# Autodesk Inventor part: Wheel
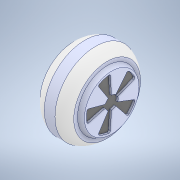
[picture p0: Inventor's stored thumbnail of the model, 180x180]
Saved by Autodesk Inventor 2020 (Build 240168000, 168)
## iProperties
Created: 2020-04
Part Number: Wheel
Material: Générique
Document SubType Name: Modeling
Designer: bruno
Density: 1 g/cm^3
Appearance: Par défaut
Sending System: SolidWorks 2017
Last Author: hpras
Last Saved: 2020-04-23
Author: bruno
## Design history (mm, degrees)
feature "CirPattern2"
sketch "Esquisse1"
  geometry: C1 r 12.7 at (0, 0); A1 r 12.7 centre (0, 0) between (6.917, -10.651) and (11.413, -5.57) reference; A2 r 12.7 centre (0, 0) between (-7.992, -9.87) and (0.665, -12.683) reference; A3 r 12.7 centre (0, 0) between (-11.856, 4.551) and (-11.856, -4.551) reference; A4 r 12.7 centre (0, 0) between (0.665, 12.683) and (-7.992, 9.87) reference; A5 r 12.7 centre (0, 0) between (11.413, 5.57) and (6.917, 10.651) reference; 11 further points
  constraints: 1 centre point, 1 coincident, 1 concentric
extrude "Extrusion1" join sketch "Esquisse1" distance "d0" = 10; taper "d1" = 0 deg
chamfer "Chanfrein1" distance "d2" = 0.5; stored, may be unused: second distance "d3" = 2, angle "d4" = 45 deg
sketch "Esquisse2"
  geometry: L1 (15.777, 80)-(-33.547, 80); L2 (-33.547, 80)-(-33.547, 89.418); L3 (-33.547, 89.418)-(15.777, 89.418); L4 (15.777, 89.418)-(15.777, 80); L5 (0, 0)-(49.987, 0)
  constraints: 10 end point, 2 horizontal, 2 parallel, 1 perpendicular
  dimensions: "d5" = 80 distance from line of L1 L5.start
revolve "Révolution1" sketch "Esquisse2" stored, may be unused: angle "d6" = 90 deg
node "Solide1"
